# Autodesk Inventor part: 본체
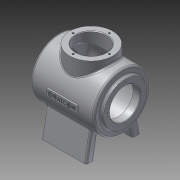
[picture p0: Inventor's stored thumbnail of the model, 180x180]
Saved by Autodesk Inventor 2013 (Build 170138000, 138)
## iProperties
Created: 2015-01
Part Number: 본체
Material: 알루미늄 6061
Document SubType Name: Modeling
Designer: Administrator
Density: 2.71 g/cm^3
Mass: 1019.38 g
Surface Area: 1059.07 cm^2
Volume: 376.154 cm^3
Author: Administrator
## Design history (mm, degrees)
sketch "스케치1"
  geometry: C1 r 50 at (0, 0); 1 further point
  constraints: 1 centre point, 1 coincident
  dimensions: "d0" = 100 diameter of C1
extrude "돌출1" new body sketch "스케치1" stored distance "d1" = 112; taper "d2" = 0 deg
node "작업 평면1"
node "작업 평면3"
sketch "스케치6"
  geometry: L1 (-48, -80)-(-34, -80); L2 (34, -80)-(48, -80); L3 (34, -80)-(27.282, -41.901); L4 (-48, -80)-(-39.336, -30.865); L5 (-34, -80)-(-27.282, -41.901); L6 (48, -80)-(39.336, -30.865); A1 r 50 centre (0, 0) between (27.282, -41.901) and (-39.336, -30.865) reference; 1 further point
  constraints: 12 end point, 4 point on circle, 2 horizontal
  dimensions: "d18" = 80 distance from line of point (0, 0) L1; "d19" = 80 distance from line of L2 point (0, 0); "d20" = 14 distance of L1.start L1.end; "d21" = 14 distance of L2.start L2.end; "d22" = 48 horizontal distance of point (0, 0) L1.start; "d23" = 48 horizontal distance of L2.end point (0, 0); "d26" = 100 deg angle of L1 L4; "d27" = 80 deg angle of L1 L5; "d28" = 80 deg angle of L2 L3; "d29" = 100 deg angle of L2 L6
extrude "돌출6" join sketch "스케치6" stored distance "d30" = 80; taper "d31" = 0 deg
sketch "스케치10"
  geometry: C1 r 50 at (0, 0) reference; C2 r 38 at (0, 0)
  constraints: 1 centre point, 1 coincident
  dimensions: "d43" = 76 diameter of C2
extrude "돌출9" join sketch "스케치10" distance "d44" = 5; taper "d45" = 0 deg
sketch "스케치11"
  geometry: C1 r 38 at (0, 0) reference; C2 r 27 at (0, 0)
  constraints: 1 centre point, 1 coincident
  dimensions: "d46" = 54 diameter of C2
extrude "돌출10" cut sketch "스케치11" distance "d47" = 13; taper "d48" = 0 deg
sketch "스케치12"
  geometry: C1 r 38 at (0, 0) reference; C2 r 27 at (0, 0)
  constraints: 1 centre point, 1 coincident
  dimensions: "d49" = 54 diameter of C2
extrude "돌출11" cut sketch "스케치12" distance "d50" = 12; taper "d51" = 0 deg
node "작업 평면5"
sketch "스케치13"
  geometry: C1 r 45 at (0, 0); 1 further point
  constraints: 1 centre point, 1 coincident
  dimensions: "d53" = 90 diameter of C1
extrude "돌출12" cut sketch "스케치13" distance "d54" = 97; taper "d55" = 0 deg
sketch "스케치16"
  geometry: C1 r 27 at (0, 0) reference; 1 further point
  constraints: 1 vertical alignment
  dimensions: "d62" = 32 distance of C1.centre point (0, 32)
hole "구멍1" sketch "스케치16" at (0, 32) diameter "d63" = 3.242; stored, may be unused: countersink angle "d67" = 90 deg, drill point angle "d69" = 118 deg; dims "d64" = 8, "d65" = 4, "d66" = 2, "d68" = 10
fillet "모깎기1" dims "d84" = 3
fillet "모깎기2" dims "d85" = 3
chamfer "모따기1" distance "d87" = 1; stored, may be unused: second distance "d88" = 2, angle "d89" = 45 deg
node "작업 평면7"
sketch "스케치18"
  geometry: L1 (-61, -38)-(-61, 38) reference; L2 (-26, 6)-(28, 6); L3 (28, 6)-(28, -6); L4 (28, -6)-(-26, -6); L5 (-26, -6)-(-26, 6); 1 further point
  constraints: 8 end point, 2 perpendicular, 1 horizontal, 1 midpoint, 1 parallel
  dimensions: "d123" = 54 distance of L2.start L2.end; "d125" = 12 distance of L4.end L2.start; "d126" = 35 distance between parallel lines of L1 L5; "d127" = 6 distance from line of point (-61, 0) L2
extrude "돌출15" join sketch "스케치18" stored distance "d93" = 97; taper "d94" = 0 deg
sketch "스케치20"
  geometry: L1 (-61, -38)-(-61, 38) reference; C1 r 38 at (1, 0); 1 further point
  constraints: 1 centre point, 1 horizontal alignment
  dimensions: "d97" = 76 diameter of C1; "d98" = 62 distance from line of L1 C1.centre
extrude "돌출16" join sketch "스케치20" stored distance "d99" = 97; taper "d100" = 0 deg
sketch "스케치21"
  geometry: C1 r 38 at (0, 0) reference; C2 r 27 at (0, 0); 1 further point
  constraints: 1 centre point, 1 coincident
  dimensions: "d101" = 54 diameter of C2
extrude "돌출17" cut sketch "스케치21" stored distance "d103" = 97; taper "d104" = 0 deg
sketch "스케치22"
  geometry: C1 r 27 at (0, 0) reference; 2 further points
  constraints: 1 vertical alignment
  dimensions: "d105" = 32 distance of C1.centre point (0, 32)
hole "구멍3" sketch "스케치22" at (0, 32) diameter "d106" = 3.242; stored, may be unused: countersink angle "d110" = 90 deg, drill point angle "d112" = 118 deg; dims "d107" = 8, "d108" = 4, "d109" = 2, "d111" = 10
fillet "모깎기4" dims "d116" = 3
chamfer "모따기2" distance "d117" = 1; stored, may be unused: second distance "d118" = 2, angle "d119" = 45 deg
sketch "스케치23"
  geometry: L1 (28, -6)-(-26, -6) reference; L2 (28, 6)-(28, -6) reference; 2 further points
  constraints: 1 other
  dimensions: "d128" = 6 distance from line of L1 point (1, 0); "d129" = 27 distance from line of L2 point (1, 0)
feature "엠보싱3" sketch "스케치23" dims "d2" = 0, "d130" = 0.5, "d131" = 0
node "솔리드1"
mirror "대칭2"
pattern_circular "원형 패턴1" dims angle "d71" = 360 deg
mirror "대칭3"
pattern_circular "원형 패턴3" dims angle "d114" = 360 deg
other parameters: "d6" = -12, "d10" = 62, "d52" = -13, "d90" = -52
